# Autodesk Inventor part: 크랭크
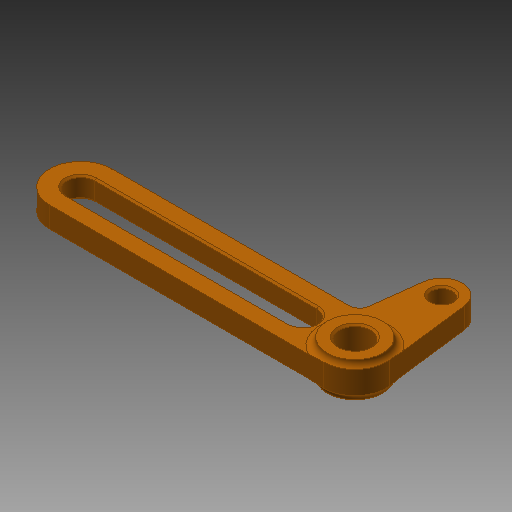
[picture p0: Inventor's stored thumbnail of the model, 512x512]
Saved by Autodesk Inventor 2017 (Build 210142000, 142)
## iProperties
Created: 2019-09
Part Number: 크랭크
Material: 알루미늄 6061
Document SubType Name: Modeling
Designer: mduedu
Density: 2.71 g/cm^3
Appearance: 주황색
Mass: 23.0159 g
Surface Area: 54.7149 cm^2
Volume: 8.49295 cm^3
Author: mduedu
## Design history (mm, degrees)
sketch "스케치1"
  geometry: L1 (0, 0)-(79, 0); L2 (0, 9)-(79, 9); L3 (10.637, -9)-(79, -9); L4 (0, 0)-(0, -25); L5 (-8.935, -1.08)-(-5.957, -25.72); L6 (7.659, -11.64)-(5.957, -25.72); L7 (79, -4)-(15, -4); L8 (15, 4)-(79, 4); C1 r 3 at (0, -25); A1 r 9 centre (0, 0) between (0, 9) and (-8.935, -1.08); A2 r 9 centre (79, 0) between (79, -9) and (79, 9); A3 r 6 centre (0, -25) between (-5.957, -25.72) and (5.957, -25.72); A4 r 3 centre (10.637, -12) between (10.637, -9) and (7.659, -11.64); A5 r 4 centre (79, 0) between (79, -4) and (79, 4); A6 r 4 centre (15, 0) between (15, -4) and (15, 4); 1 further point
  constraints: 16 end point, 13 point on circle, 12 tangent, 7 centre point, 5 coincident, 3 horizontal, 2 point on line, 1 equal radius, 1 perpendicular, 1 other
  dimensions: "d0" = 79 distance of L1.start L1.end; "d2" = 25 distance of L1.start L4.end; "d3" = 3 radius of A4; "d4" = 9 radius of A1; "d5" = 6 radius of A3; "d6" = 8 diameter of A5; "d7" = 64 distance of A6.centre L1.end; "d8" = 6 diameter of C1
extrude "돌출1" new body sketch "스케치1" stored distance "d9" = 6; taper "d10" = 0 deg
sketch "스케치2"
  geometry: C1 r 8 at (0, 0); 1 further point
  constraints: 1 centre point, 1 coincident
  dimensions: "d11" = 16 diameter of C1
extrude "돌출2" join sketch "스케치2" stored distance "d12" = 10; taper "d13" = 0 deg
sketch "스케치3"
  geometry: C1 r 4.5 at (0, 0); 1 further point
  constraints: 1 centre point, 1 coincident
  dimensions: "d14" = 9 diameter of C1
extrude "돌출3" cut sketch "스케치3" stored distance "d15" = 10; taper "d16" = 0 deg
fillet "모깎기1" dims "d17" = 2
chamfer "모따기1" distance "d18" = 0.5; stored, may be unused: second distance "d19" = 2, angle "d20" = 45 deg
node "솔리드1"
